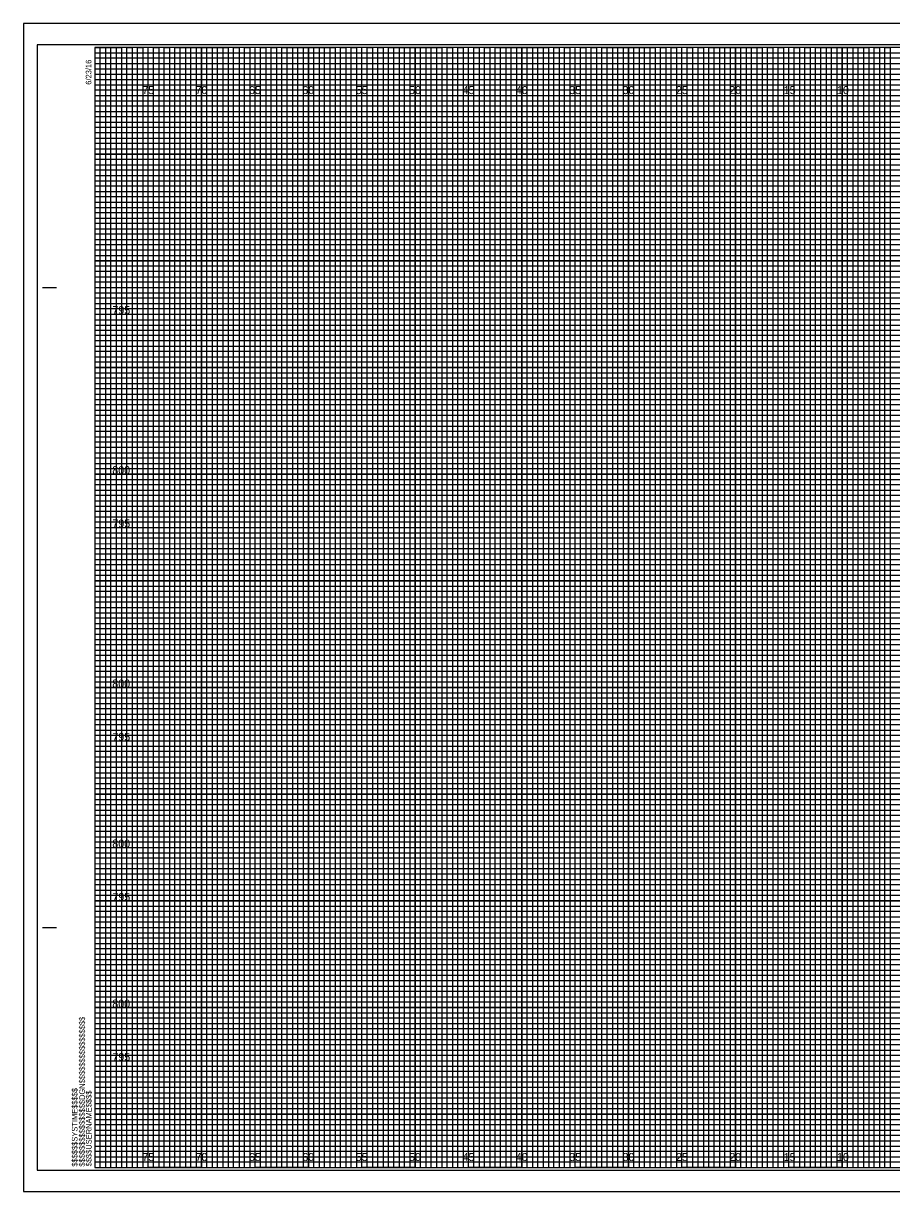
# Model space of a CAD drawing. Extents: x -7 to 162, y -2 to 107.
# Drawn here: x -6.7 to 74.6, y -2.3 to 107.3 of the extents above; entities that cross this region are included whole.
import ezdxf

# ---------------------------------------------------------------- set-up
doc = ezdxf.new("R2010")
doc.units = 0
for name, color, linetype in [('Prop XS Elevation Labels', 7, 'Continuous'), ('Prop XS Offset Labels', 7, 'Continuous'), ('Sheet Cross Section CELL', 7, 'Continuous'), ('Sheet Cross Section Grid Major CELL', 7, 'Continuous'), ('Sheet Cross Section Grid Middle CELL', 7, 'Continuous'), ('Sheet Cross Section Grid Minor 1 CELL', 7, 'Continuous'), ('Sheet Cross Section Grid Minor 2 CELL', 7, 'Continuous'), ('Sheet Cutting Line CELL', 7, 'Continuous'), ('Sheet DOT Grid CELL', 7, 'Continuous'), ('Sheet Plot Border Inside CELL', 7, 'Continuous'), ('Sheet Plot Border Outside CELL', 7, 'Continuous')]:
    doc.layers.add(name, color=color, linetype=linetype)

msp = doc.modelspace()

# ---------------------------------------------------------------- linework, layer by layer
at = {"layer": 'Sheet Cross Section CELL'}
for p, q in [((-4.9, 82.5), (-3.65, 82.5)), ((-4.85, 82.5), (-3.6, 82.5)), ((-4.9, 22.5), (-3.65, 22.5)), ((-4.85, 22.5), (-3.6, 22.5)), ((0, 0), (0, 0)), ((0, 0), (0, 0)), ((0, 0), (0, 0)), ((0, 0), (0, 0)), ((0, 0), (0, 0)), ((0, 0), (0, 0)), ((0, 0), (0, 0))]:
    msp.add_line(p, q, dxfattribs=at)
msp.add_lwpolyline([(160, 105), (0, 105), (0, 0), (160, 0)], close=True, dxfattribs=at)
at = {"layer": 'Sheet Cross Section Grid Major CELL'}
for p, q in [((5, 105), (0, 105)), ((5, 0), (5, 105)), ((15, 105), (10, 105)), ((10, 105), (10, 0)), ((15, 0), (15, 105)), ((25, 105), (20, 105)), ((20, 105), (20, 0)), ((25, 0), (25, 105)), ((35, 105), (30, 105)), ((30, 105), (30, 0)), ((35, 0), (35, 105)), ((45, 105), (40, 105)), ((40, 105), (40, 0)), ((45, 0), (45, 105)), ((55, 105), (50, 105)), ((50, 105), (50, 0)), ((55, 0), (55, 105)), ((65, 105), (60, 105)), ((60, 105), (60, 0)), ((65, 0), (65, 105)), ((75, 105), (70, 105)), ((70, 105), (70, 0)), ((10, 0), (5, 0)), ((20, 0), (15, 0)), ((30, 0), (25, 0)), ((40, 0), (35, 0)), ((50, 0), (45, 0)), ((60, 0), (55, 0)), ((70, 0), (65, 0))]:
    msp.add_line(p, q, dxfattribs=at)
for points in [[(0, 100), (160, 100), (160, 95), (0, 95)], [(0, 90), (160, 90), (160, 85), (0, 85)], [(0, 80), (160, 80), (160, 75), (0, 75)], [(0, 70), (160, 70), (160, 65), (0, 65)], [(0, 60), (160, 60), (160, 55), (0, 55)], [(0, 50), (160, 50), (160, 45), (0, 45)], [(0, 40), (160, 40), (160, 35), (0, 35)], [(0, 30), (160, 30), (160, 25), (0, 25)], [(0, 20), (160, 20), (160, 15), (0, 15)], [(0, 10), (160, 10), (160, 5), (0, 5)]]:
    msp.add_lwpolyline(points, dxfattribs=at)
at = {"layer": 'Sheet Cross Section Grid Middle CELL'}
for points in [[(0, 105), (2.5, 105), (2.5, 0), (7.5, 0), (7.5, 105), (12.5, 105), (12.5, 0), (17.5, 0), (17.5, 105), (22.5, 105), (22.5, 0), (27.5, 0), (27.5, 105), (32.5, 105), (32.5, 0), (37.5, 0), (37.5, 105), (42.5, 105), (42.5, 0), (47.5, 0), (47.5, 105), (52.5, 105), (52.5, 0), (57.5, 0), (57.5, 105), (62.5, 105), (62.5, 0), (67.5, 0), (67.5, 105), (72.5, 105), (72.5, 0), (77.5, 0)], [(0, 102.5), (137.5, 102.5)], [(0, 92.5), (160, 92.5), (160, 97.5), (0, 97.5)], [(0, 82.5), (160, 82.5), (160, 87.5), (0, 87.5)], [(0, 72.5), (160, 72.5), (160, 77.5), (0, 77.5)], [(0, 62.5), (160, 62.5), (160, 67.5), (0, 67.5)], [(0, 52.5), (160, 52.5), (160, 57.5), (0, 57.5)], [(0, 42.5), (160, 42.5), (160, 47.5), (0, 47.5)], [(0, 32.5), (160, 32.5), (160, 37.5), (0, 37.5)], [(0, 22.5), (160, 22.5), (160, 27.5), (0, 27.5)], [(0, 12.5), (160, 12.5), (160, 17.5), (0, 17.5)], [(0, 2.5), (160, 2.5), (160, 7.5), (0, 7.5)]]:
    msp.add_lwpolyline(points, dxfattribs=at)
at = {"layer": 'Sheet Cross Section Grid Minor 1 CELL'}
for p, q in [((0, 104.5), (130, 104.5)), ((130, 103.99), (0, 103.99)), ((0, 103.99), (0, 103.5)), ((0, 103.5), (130, 103.5)), ((130, 102.95), (0, 102.95)), ((0, 102.95), (0, 102)), ((0, 102), (160, 102))]:
    msp.add_line(p, q, dxfattribs=at)
for points in [[(0, 101.5), (135, 101.5), (160, 101.5), (160, 101), (0, 101)], [(0, 100.5), (160, 100.5), (160, 99.5), (0, 99.5)], [(0, 99), (160, 99), (160, 98.5), (0, 98.49)], [(0, 98), (160, 98), (160, 97), (0, 97)], [(0, 96.5), (160, 96.5), (160, 96), (0, 96)], [(0, 95.5), (160, 95.5), (160, 94.5), (0, 94.5)], [(0, 94), (160, 94), (160, 93.5), (0, 93.5)], [(0, 93), (160, 93), (160, 92), (0, 92)], [(0, 91.5), (160, 91.5), (160, 91), (0, 91)], [(0, 90.5), (160, 90.5), (160, 89.5), (0, 89.5)], [(0, 89), (160, 89), (160, 88.5), (0, 88.5)], [(0, 88), (160, 88), (160, 86.98), (160, 86.5), (160, 86), (0, 86)], [(0, 87), (160, 87), (160, 86.5), (0, 86.5)], [(0, 85.5), (160, 85.5), (160, 84.5), (0, 84.52)], [(0, 84.52), (160, 84.5), (160, 84), (0, 84)], [(0, 83.5), (160, 83.5), (160, 83), (0, 83)], [(0, 82), (160, 82), (160, 81.5), (0, 81.5)], [(0, 81), (160, 81), (160, 80.5), (0, 80.5)], [(-0.04, 79.45), (160, 79.45), (160, 78.94), (-0.04, 78.94)], [(0, 78.5), (160, 78.5), (160, 78), (0, 78)], [(0, 77), (160, 77), (160, 76.5), (0, 76.5)], [(0, 76), (160, 76), (160, 75.5), (0, 75.5)], [(0, 74.5), (160, 74.5), (160, 74), (0, 74)], [(0, 73.5), (160, 73.5), (160, 73), (0, 73)], [(0, 72), (160, 72), (160, 71.5), (0, 71.5)], [(0, 71), (160, 71), (160, 70.5), (0, 70.5)], [(0, 69.5), (160, 69.5), (160, 68.99), (0, 69)], [(0, 68.5), (160, 68.5), (160, 68), (0, 68)], [(0, 67), (160, 67), (160, 66.5), (0, 66.5)], [(0, 66), (160, 66), (160, 65.5), (0, 65.5)], [(0, 64.5), (160, 64.5), (160, 64), (0, 64)], [(0, 63.5), (160, 63.5), (160, 63), (0, 63)], [(0, 62), (160, 62), (160, 61.5), (0, 61.5)], [(0, 61), (160, 61), (160, 60.5), (0, 60.5)], [(0, 59.5), (160, 59.5), (160, 59), (0, 59)], [(0, 58.5), (160.03, 58.45), (160, 58), (0, 58)], [(0, 57), (160, 57), (160, 56.5), (0, 56.5)], [(0, 56), (160, 56), (160, 55.5), (0, 55.5)], [(0, 54.5), (160, 54.5), (160, 54), (0, 54)], [(0, 53.5), (160, 53.5), (160, 53), (0, 53)], [(0, 52), (160, 52), (160, 51.5), (0, 51.5)], [(0, 51), (160, 51), (160, 50.5), (0, 50.5)], [(0, 49.5), (160, 49.5), (160, 49), (0, 49)], [(0, 48.5), (160, 48.5), (160, 48), (0, 48)], [(0, 47), (160, 47), (160, 46.5), (0, 46.5)], [(0, 46), (160, 46), (160, 45.5), (0, 45.5)], [(0, 44.5), (160, 44.5), (160, 44), (0, 44)], [(0, 43.5), (160, 43.5), (160, 43), (0, 43)], [(0, 42), (160, 42), (160, 41.5), (0, 41.5)], [(0, 41), (160, 41), (160, 40.5), (0, 40.5)], [(0, 39.5), (160, 39.5), (160, 38.99), (0, 39)], [(0, 38.5), (160, 38.5), (160, 38), (0, 38)], [(0, 37), (160, 37), (160, 36.5), (0, 36.5)], [(0, 36), (160, 36), (160, 35.5), (0, 35.5)], [(0, 34.5), (160, 34.5), (160, 34), (0, 34)], [(0, 33.5), (160, 33.5), (160, 33), (0, 33)], [(0, 32), (160, 32), (160, 31.5), (0, 31.5)], [(0, 31), (160, 31), (160, 30.5), (0, 30.5)], [(0, 29.5), (160, 29.5), (160, 29), (0, 29)], [(0, 28.5), (160.03, 28.46), (160, 28), (0, 28)], [(0, 27), (160, 27), (160, 26.5), (0, 26.5)], [(0, 26), (160, 26), (160, 25.5), (0, 25.5)], [(0, 24.5), (160, 24.5), (160, 24), (0, 24)], [(0, 23.5), (160, 23.5), (160, 23), (0, 23)], [(0, 22), (160, 22), (160, 21.5), (0, 21.5)], [(0, 21), (160, 21), (160, 20.5), (0, 20.5)], [(0, 19.5), (160, 19.5), (160, 19), (0, 19)], [(0, 18.5), (160, 18.5), (160, 18), (0, 18)], [(0, 17), (160, 17), (160, 16.5), (0, 16.5)], [(0, 16), (160, 16), (160, 15.5), (0, 15.5)], [(0, 14.5), (160, 14.5), (160, 14), (0, 14)], [(0, 13.5), (160, 13.5), (160, 13), (0, 13)], [(0, 12), (160, 12), (160, 11.5), (0, 11.5)], [(0, 11), (160, 11), (160, 10.5), (0, 10.5)], [(0, 9.5), (160, 9.5), (160, 9), (0, 9)], [(0, 8.5), (160, 8.5), (160, 8), (0, 8)], [(0, 7), (160, 7), (160, 6.5), (0, 6.5)], [(0, 6), (160, 6), (160, 5.5), (0, 5.5)], [(0, 4.5), (160, 4.5), (160, 4), (0, 4)], [(0, 3.5), (160, 3.5), (160, 3), (0, 3)], [(0, 2), (160, 2), (160, 1.5), (0, 1.5)], [(0, 1), (160, 1), (160, 0.5), (0, 0.5)]]:
    msp.add_lwpolyline(points, dxfattribs=at)
at = {"layer": 'Sheet Cross Section Grid Minor 2 CELL'}
for points in [[(0, 0), (0.5, 0), (0.5, 105), (1, 105), (1, 0)], [(1, 0), (1.5, 0), (1.5, 105), (2, 105), (2, 0)], [(2.5, 0), (3, 0), (3, 105), (3.5, 105), (3.5, 0)], [(3.5, 0), (4, 0), (4, 105), (4.5, 105), (4.5, 0)], [(5, 0), (5.5, 0), (5.5, 105), (6, 105), (6, 0)], [(6, 0), (6.5, 0), (6.5, 105), (7, 105), (7, 0)], [(7.5, 0), (8, 0), (8, 105), (8.5, 105), (8.5, 0)], [(8.5, 0), (9, 0), (9, 105), (9.5, 105), (9.5, 0)], [(10, 0), (10.5, 0), (10.5, 105), (11, 105), (11, 0)], [(11, 0), (11.5, 0), (11.5, 105), (12, 105), (12, 0)], [(12.5, 0), (13, 0), (13, 105), (13.5, 105), (13.5, 0)], [(13.5, 0), (14, 0), (14, 105), (14.5, 105), (14.5, 0)], [(15, 0), (15.5, 0), (15.5, 105), (16, 105), (16, 0)], [(16, 0), (16.5, 0), (16.5, 105), (17, 105), (17, 0)], [(17.5, 0), (18, 0), (18, 105), (18.5, 105), (18.5, 0)], [(18.5, 0), (19, 0), (19, 105), (19.5, 105), (19.5, 0)], [(20, 0), (20.5, 0), (20.5, 105), (21, 105), (21, 0)], [(21, 0), (21.5, 0), (21.5, 105), (22, 105), (22, 0)], [(22.5, 0), (23, 0), (23, 105), (23.5, 105), (23.5, 0)], [(23.5, 0), (24, 0), (24, 105), (24.5, 105), (24.5, 0)], [(25, 0), (25.5, 0), (25.5, 105), (26, 105), (26, 0)], [(26, 0), (26.5, 0), (26.5, 105), (27, 105), (27, 0)], [(27.5, 0), (28, 0), (28, 105), (28.5, 105), (28.5, 0)], [(28.5, 0), (29, 0), (29, 105), (29.5, 105), (29.5, 0)], [(30, 0), (30.5, 0), (30.5, 105), (31, 105), (31, 0)], [(31, 0), (31.5, 0), (31.5, 105), (32, 105), (32, 0)], [(32.5, 0), (33, 0), (33, 105), (33.5, 105), (33.5, 0)], [(33.5, 0), (34, 0), (34, 105), (34.5, 105), (34.5, 0)], [(35, 0), (35.5, 0), (35.5, 105), (36, 105), (36, 0)], [(36, 0), (36.5, 0), (36.5, 105), (37, 105), (37, 0)], [(37.5, 0), (38, 0), (38, 105), (38.5, 105), (38.5, 0)], [(38.5, 0), (39, 0), (39, 105), (39.5, 105), (39.5, 0)], [(40, 0), (40.5, 0), (40.5, 105), (41, 105), (41, 0)], [(41, 0), (41.5, 0), (41.5, 105), (42, 105), (42, 0)], [(42.5, 0), (43, 0), (43, 105), (43.5, 105), (43.5, 0)], [(43.5, 0), (44, 0), (44, 105), (44.5, 105), (44.5, 0)], [(45, 0), (45.5, 0), (45.5, 105), (46, 105), (46, 0)], [(46, 0), (46.5, 0), (46.5, 105), (47, 105), (47, 0)], [(47.5, 0), (48, 0), (48, 105), (48.5, 105), (48.5, 0)], [(48.5, 0), (49, 0), (49, 105), (49.5, 105), (49.5, 0)], [(50, 0), (50.5, 0), (50.5, 105), (51, 105), (51, 0)], [(51, 0), (51.5, 0), (51.5, 105), (52, 105), (52, 0)], [(52.5, 0), (53, 0), (53, 105), (53.5, 105), (53.5, 0)], [(53.5, 0), (54, 0), (54, 105), (54.5, 105), (54.5, 0)], [(55, 0), (55.5, 0), (55.5, 105), (56, 105), (56, 0)], [(56, 0), (56.5, 0), (56.5, 105), (57, 105), (57, 0)], [(57.5, 0), (58, 0), (58, 105), (58.5, 105), (58.5, 0)], [(58.5, 0), (59, 0), (59, 105), (59.5, 105), (59.5, 0)], [(60, 0), (60.5, 0), (60.5, 105), (61, 105), (61, 0)], [(61, 0), (61.5, 0), (61.5, 105), (62, 105), (62, 0)], [(62.5, 0), (63, 0), (63, 105), (63.5, 105), (63.5, 0)], [(63.5, 0), (64, 0), (64, 105), (64.5, 105), (64.5, 0)], [(65, 0), (65.5, 0), (65.5, 105), (66, 105), (66, 0)], [(66, 0), (66.5, 0), (66.5, 105), (67, 105), (67, 0)], [(67.5, 0), (68, 0), (68, 105), (68.5, 105), (68.5, 0)], [(68.5, 0), (69, 0), (69, 105), (69.5, 105), (69.5, 0)], [(70, 0), (70.5, 0), (70.5, 105), (71, 105), (71, 0)], [(71, 0), (71.5, 0), (71.5, 105), (72, 105), (72, 0)], [(72.5, 0), (73, 0), (73, 105), (73.5, 105), (73.5, 0)], [(73.5, 0), (74, 0), (74, 105), (74.5, 105), (74.5, 0)]]:
    msp.add_lwpolyline(points, dxfattribs=at)
at = {"layer": 'Sheet Cutting Line CELL'}
for p, q in [((161.65, 107.25), (-6.7, 107.25)), ((-6.7, 107.25), (-6.7, -2.25)), ((-6.7, -2.25), (161.65, -2.25))]:
    msp.add_line(p, q, dxfattribs=at)
at = {"layer": 'Sheet DOT Grid CELL'}
for p, q in [((5, 0), (5, 105)), ((10, 0), (10, 105)), ((15, 0), (15, 105)), ((20, 0), (20, 105)), ((25, 0), (25, 105)), ((30, 0), (30, 105)), ((35, 0), (35, 105)), ((40, 0), (40, 105)), ((45, 0), (45, 105)), ((50, 0), (50, 105)), ((55, 0), (55, 105)), ((60, 0), (60, 105)), ((65, 0), (65, 105)), ((70, 0), (70, 105)), ((0, 100), (160, 100)), ((0, 95), (160, 95)), ((0, 90), (160, 90)), ((0, 85), (160, 85)), ((0, 80), (160, 80)), ((0, 75), (160, 75)), ((0, 70), (160, 70)), ((0, 65), (160, 65)), ((0, 60), (160, 60)), ((0, 55), (160, 55)), ((0, 50), (160, 50)), ((0, 45), (160, 45)), ((0, 40), (160, 40)), ((0, 35), (160, 35)), ((0, 30), (160, 30)), ((0, 25), (160, 25)), ((0, 20), (160, 20)), ((0, 15), (160, 15)), ((0, 10), (160, 10)), ((0, 5), (160, 5))]:
    msp.add_line(p, q, dxfattribs=at)
at = {"layer": 'Sheet Plot Border Inside CELL'}
msp.add_lwpolyline([(-5.4, -0.25), (161.2, -0.25), (161.2, 105.25), (-5.4, 105.25)], close=True, dxfattribs=at)
at = {"layer": 'Sheet Plot Border Outside CELL'}
msp.add_lwpolyline([(-6.7, -2.25), (161.65, -2.25), (161.65, 107.25), (-6.7, 107.25)], close=True, dxfattribs=at)

# ---------------------------------------------------------------- texts
at = {"layer": 'Prop XS Elevation Labels'}
for s, p in [('795', (1.64, 80)), ('800', (1.63, 65)), ('795', (1.64, 60)), ('800', (1.63, 45)), ('795', (1.64, 40)), ('800', (1.63, 30)), ('795', (1.64, 25)), ('800', (1.63, 15)), ('795', (1.64, 10))]:
    msp.add_text(s, height=0.75, dxfattribs=at).set_placement(p)
at = {"layer": 'Prop XS Offset Labels'}
for s, p in [('75', (4.44, 100.62)), ('70', (9.43, 100.62)), ('65', (14.44, 100.62)), ('60', (19.43, 100.62)), ('55', (24.44, 100.62)), ('50', (29.43, 100.62)), ('45', (34.44, 100.62)), ('40', (39.43, 100.62)), ('35', (44.44, 100.62)), ('30', (49.43, 100.62)), ('25', (54.44, 100.62)), ('20', (59.43, 100.62)), ('15', (64.53, 100.62)), ('10', (69.52, 100.62)), ('75', (4.44, 0.62)), ('70', (9.43, 0.62)), ('65', (14.44, 0.62)), ('60', (19.43, 0.62)), ('55', (24.44, 0.62)), ('50', (29.43, 0.62)), ('45', (34.44, 0.62)), ('40', (39.43, 0.62)), ('35', (44.44, 0.62)), ('30', (49.43, 0.62)), ('25', (54.44, 0.62)), ('20', (59.43, 0.62)), ('15', (64.53, 0.62)), ('10', (69.52, 0.62))]:
    msp.add_text(s, height=0.75, dxfattribs=at).set_placement(p)
at = {"layer": 'Sheet Cross Section CELL'}
for s, p in [('6/23/16', (-0.33, 101.5)), ('$$$$$$$$$$$$$$$$DGN$$$$$$$$$$$$$$$$', (-0.94, 0.09)), ('$$$$$$SYSTIME$$$$$', (-1.63, 0.09)), ('$$$$USERNAME$$$$', (-0.31, 0.12))]:
    msp.add_text(s, height=0.525, rotation=90, dxfattribs=at).set_placement(p)

doc.saveas('drawing.dxf')
